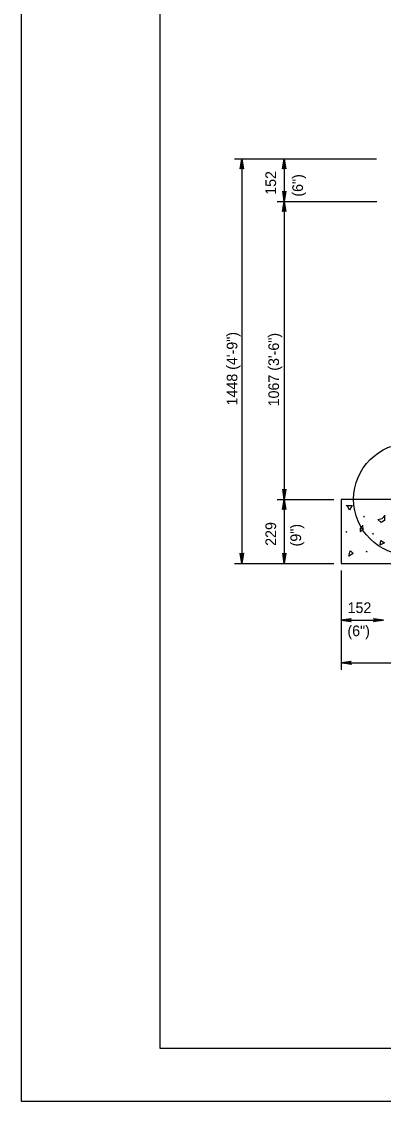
# Model space of a CAD drawing. Extents: x 638443 to 639347, y 298405 to 298999.
# Drawn here: x 638443.3 to 638545.3, y 298405 to 298709.2 of the extents above; entities that cross this region are included whole.
import ezdxf

# ---------------------------------------------------------------- set-up
doc = ezdxf.new("R2010")
doc.units = 0
for name, color, linetype in [('1', 7, 'Continuous'), ('2', 7, 'Continuous'), ('3', 7, 'Continuous'), ('PLT-BNDY', 7, 'Continuous')]:
    doc.layers.add(name, color=color, linetype=linetype)

msp = doc.modelspace()

# ---------------------------------------------------------------- linework, layer by layer
at = {"layer": '1'}
msp.add_lwpolyline([(639268.31, 298419.95), (639268.31, 298983.95), (638482.31, 298983.95), (638482.31, 298419.95), (639268.31, 298419.95), (639268.31, 298446.31), (639068.31, 298446.31), (639068.31, 298510.99), (639268.31, 298510.99), (639268.31, 298539.95), (639068.31, 298539.95), (639068.31, 298419.95), (639147.11, 298419.95), (639147.11, 298446.31), (639147.11, 298419.95), (639224.11, 298419.95), (639224.11, 298446.31), (639224.11, 298434), (639268.31, 298434)], dxfattribs=at)
at = {"layer": '2'}
for p, q in [((638503.34, 298670.58), (638543.34, 298670.58)), ((638505.34, 298670.58), (638505.34, 298556.58)), ((638517.34, 298670.58), (638517.34, 298658.58)), ((638515.34, 298658.58), (638543.41, 298658.58)), ((638517.34, 298658.58), (638517.34, 298574.58)), ((638515.34, 298574.58), (638531.34, 298574.58)), ((638517.34, 298574.58), (638517.34, 298556.58)), ((638677.34, 298574.58), (638533.34, 298574.58)), ((638533.34, 298574.58), (638533.34, 298556.58)), ((638503.34, 298556.58), (638531.34, 298556.58)), ((638533.34, 298556.58), (638677.34, 298556.58)), ((638533.34, 298554.58), (638533.34, 298526.58)), ((638533.34, 298540.58), (638545.34, 298540.58)), ((638533.34, 298528.58), (638677.34, 298528.58))]:
    msp.add_line(p, q, dxfattribs=at)
for points in [[(638505, 298667.86), (638505.2, 298667.96), (638505.34, 298670.58), (638505, 298667.86), (638504.88, 298667.72), (638505.34, 298670.58), (638505.47, 298667.96), (638505.67, 298667.87), (638505.34, 298670.58), (638505.8, 298667.72), (638505.67, 298667.87)], [(638517, 298667.86), (638517.2, 298667.96), (638517.34, 298670.58), (638517, 298667.86), (638516.88, 298667.72), (638517.34, 298670.58), (638517.47, 298667.96), (638517.67, 298667.87), (638517.34, 298670.58), (638517.8, 298667.72), (638517.67, 298667.87)], [(638517.68, 298661.31), (638517.49, 298661.21), (638517.34, 298658.58), (638517.68, 298661.31), (638517.8, 298661.45), (638517.34, 298658.58), (638517.21, 298661.2), (638517.02, 298661.3), (638517.34, 298658.58), (638516.89, 298661.45), (638517.02, 298661.3)], [(638517, 298655.86), (638517.2, 298655.96), (638517.34, 298658.58), (638517, 298655.86), (638516.88, 298655.72), (638517.34, 298658.58), (638517.47, 298655.96), (638517.67, 298655.87), (638517.34, 298658.58), (638517.8, 298655.72), (638517.67, 298655.87)], [(638517.68, 298577.31), (638517.49, 298577.21), (638517.34, 298574.58), (638517.68, 298577.31), (638517.8, 298577.45), (638517.34, 298574.58), (638517.21, 298577.2), (638517.02, 298577.3), (638517.34, 298574.58), (638516.89, 298577.45), (638517.02, 298577.3)], [(638517, 298571.86), (638517.2, 298571.96), (638517.34, 298574.58), (638517, 298571.86), (638516.88, 298571.72), (638517.34, 298574.58), (638517.47, 298571.96), (638517.67, 298571.87), (638517.34, 298574.58), (638517.8, 298571.72), (638517.67, 298571.87)], [(638505.68, 298559.31), (638505.49, 298559.21), (638505.34, 298556.58), (638505.68, 298559.31), (638505.8, 298559.45), (638505.34, 298556.58), (638505.21, 298559.2), (638505.02, 298559.3), (638505.34, 298556.58), (638504.89, 298559.45), (638505.02, 298559.3)], [(638517.68, 298559.31), (638517.49, 298559.21), (638517.34, 298556.58), (638517.68, 298559.31), (638517.8, 298559.45), (638517.34, 298556.58), (638517.21, 298559.2), (638517.02, 298559.3), (638517.34, 298556.58), (638516.89, 298559.45), (638517.02, 298559.3)], [(638536.07, 298540.24), (638535.96, 298540.44), (638533.34, 298540.58), (638536.07, 298540.24), (638536.21, 298540.12), (638533.34, 298540.58), (638535.96, 298540.71), (638536.06, 298540.91), (638533.34, 298540.58), (638536.21, 298541.04), (638536.06, 298540.91)], [(638542.62, 298540.93), (638542.72, 298540.73), (638545.34, 298540.58), (638542.62, 298540.93), (638542.48, 298541.05), (638545.34, 298540.58), (638542.72, 298540.45), (638542.63, 298540.26), (638545.34, 298540.58), (638542.48, 298540.13), (638542.63, 298540.26)], [(638536.07, 298528.24), (638535.96, 298528.44), (638533.34, 298528.58), (638536.07, 298528.24), (638536.21, 298528.12), (638533.34, 298528.58), (638535.96, 298528.71), (638536.06, 298528.91), (638533.34, 298528.58), (638536.21, 298529.04), (638536.06, 298528.91)]]:
    msp.add_lwpolyline(points, dxfattribs=at)
at = {"layer": '3'}
for points in [[(638534.88, 298572.89), (638536.44, 298572.89), (638535.72, 298571.57), (638535.35, 298572.41), (638534.75, 298573)], [(638545.6, 298570.17), (638545.54, 298568.62), (638544.61, 298568.08), (638543.68, 298568.94), (638544.9, 298569.23), (638545.66, 298570.08)], [(638539.48, 298567.23), (638538.76, 298566.4), (638538.76, 298565.56), (638539.6, 298566.05), (638539.48, 298567.36)], [(638544.4, 298561.7), (638544.53, 298563.02), (638545.61, 298562.32), (638544.29, 298561.7)], [(638536, 298560.15), (638536.72, 298559.31), (638535.51, 298558.59), (638535.87, 298560.15)]]:
    msp.add_lwpolyline(points, dxfattribs=at)
msp.add_circle((638552.7, 298574.63), 15.81, dxfattribs=at)
at = {"layer": 'PLT-BNDY'}
msp.add_lwpolyline([(638443.31, 298998.95), (639284.31, 298998.95), (639284.31, 298404.95), (638443.31, 298404.95)], close=True, dxfattribs=at)

# ---------------------------------------------------------------- texts
at = {"layer": '3'}
for s, rotation, p in [('152', 90, (638515.03, 298660.44)), ('(6")', 90, (638522.6, 298659.92)), ('1448 (4\'-9")', 90, (638504.12, 298601.08)), ('1067 (3\'-6")', 90, (638515.86, 298600.82)), ('229', 90, (638515.03, 298561.51)), ('.', 210, (638540.19, 298570.22)), ('(9")', 90, (638522.08, 298561.35)), ('.', 210, (638535.22, 298565.93)), ('.', 210, (638542.71, 298565.41)), ('.', 210, (638540.91, 298560.39))]:
    msp.add_text(s, height=3, rotation=rotation, dxfattribs=at).set_placement(p)
for s, p in [('152', (638535.19, 298542.58)), ('(6")', (638535.14, 298536.06))]:
    msp.add_text(s, height=3, dxfattribs=at).set_placement(p)

doc.saveas('drawing.dxf')
